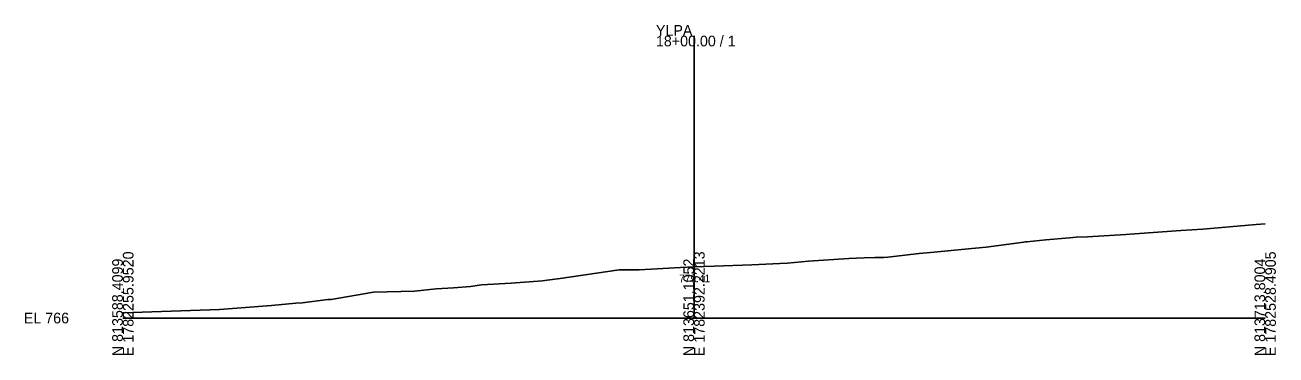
# Model space of a CAD drawing. Extents: x -76 to 1303, y -10 to 9544.
# Drawn here: x -25.7 to 302.8, y 7990.3 to 8076.9 of the extents above; entities that cross this region are included whole.
import ezdxf

# ---------------------------------------------------------------- set-up
doc = ezdxf.new("R2010")
doc.units = 0
for name, color, linetype in [('Exist Cross Section Cell', 7, 'Continuous'), ('Exist XS Center Line Elevation Label', 7, 'Continuous'), ('Exist XS Ground Line', 7, 'Continuous')]:
    doc.layers.add(name, color=color, linetype=linetype)

msp = doc.modelspace()

# ---------------------------------------------------------------- linework, layer by layer
at = {"layer": 'Exist Cross Section Cell'}
for p, q in [((150, 8000), (150, 8074.12)), ((0, 8000), (150, 8000)), ((150, 8000), (300, 8000))]:
    msp.add_line(p, q, dxfattribs=at)
at = {"layer": 'Exist XS Ground Line'}
for p, q in [((265.76, 8022.09), (277.84, 8022.98)), ((277.84, 8022.98), (283.61, 8023.3)), ((283.61, 8023.3), (297.62, 8024.53)), ((297.62, 8024.53), (300, 8024.71)), ((226.75, 8018.61), (236.6, 8019.92)), ((236.6, 8019.92), (237.06, 8019.98)), ((237.06, 8019.98), (237.37, 8020.01)), ((237.37, 8020.01), (242.41, 8020.53)), ((242.41, 8020.53), (248.65, 8021.06)), ((248.65, 8021.06), (250.37, 8021.2)), ((250.37, 8021.2), (253.31, 8021.36)), ((253.31, 8021.36), (263.43, 8021.95)), ((263.43, 8021.95), (265.76, 8022.09)), ((200.93, 8015.97), (209.13, 8016.97)), ((209.13, 8016.97), (213.07, 8017.32)), ((213.07, 8017.32), (221.16, 8018.06)), ((221.16, 8018.06), (226.75, 8018.61)), ((138.75, 8012.83), (146.47, 8013.29)), ((146.47, 8013.29), (150, 8013.41)), ((150, 8013.41), (155.26, 8013.6)), ((155.26, 8013.6), (165.22, 8014.01)), ((165.22, 8014.01), (172.5, 8014.32)), ((172.5, 8014.32), (174.55, 8014.43)), ((174.55, 8014.43), (180.07, 8014.95)), ((180.07, 8014.95), (190.65, 8015.67)), ((190.65, 8015.67), (194.7, 8015.84)), ((194.7, 8015.84), (197.45, 8015.87)), ((197.45, 8015.87), (199.89, 8015.91)), ((199.89, 8015.91), (200.93, 8015.97)), ((102.02, 8009.15), (110.17, 8009.8)), ((110.17, 8009.8), (111.4, 8009.91)), ((111.4, 8009.91), (114.89, 8010.39)), ((114.89, 8010.39), (130.38, 8012.63)), ((130.38, 8012.63), (135.11, 8012.65)), ((135.11, 8012.65), (135.63, 8012.68)), ((135.63, 8012.68), (138.75, 8012.83)), ((54.75, 8004.91), (65.79, 8006.83)), ((65.79, 8006.83), (76.59, 8007.05)), ((76.59, 8007.05), (82.27, 8007.63)), ((82.27, 8007.63), (86.86, 8007.97)), ((86.86, 8007.97), (91.28, 8008.31)), ((91.28, 8008.31), (94.16, 8008.68)), ((94.16, 8008.68), (102.02, 8009.15)), ((25.4, 8002.24), (39.01, 8003.3)), ((39.01, 8003.3), (45.41, 8003.92)), ((45.41, 8003.92), (47.05, 8004.02)), ((47.05, 8004.02), (53.86, 8004.88)), ((53.86, 8004.88), (54.75, 8004.91)), ((0, 8001.41), (25.4, 8002.24))]:
    msp.add_line(p, q, dxfattribs=at)

# ---------------------------------------------------------------- texts
at = {"layer": 'Exist Cross Section Cell'}
for s, p in [('YLPA', (140, 8074.12)), ('18+00.00 / 1', (140, 8071.32)), ('EL 766', (-26, 7998.6))]:
    msp.add_text(s, height=2.8, dxfattribs=at).set_placement(p)
for s, p in [('E 1782255.9520', (2.8, 7990)), ('E 1782392.2213', (152.8, 7990)), ('E 1782528.4905', (302.8, 7990)), ('N 813588.4099', (0, 7990)), ('N 813651.1052', (150, 7990)), ('N 813713.8004', (300, 7990))]:
    msp.add_text(s, height=2.8, rotation=90, dxfattribs=at).set_placement(p)
at = {"layer": 'Exist XS Center Line Elevation Label'}
msp.add_text('779.41', height=2, dxfattribs=at).set_placement((146.08, 8009.41))

doc.saveas('drawing.dxf')
